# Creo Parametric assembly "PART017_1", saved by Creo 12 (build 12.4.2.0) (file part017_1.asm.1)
Units: Custom; MM, KILOGRAM, SECS

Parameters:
  PTC_WM_ITERATION = "0"
  PTC_WM_VERSION = "-.0"
  PTC_WM_LIFECYCLE_STATE = "In Work"
  PTC_WM_LIFECYCLE = "MO_CADDocument"
  PTC_WM_CREATED_BY = "Maximilian Roepper (Z0017RMS: MO)"
  PTC_WM_CREATED_ON = "18-Sep-26 11:36:42 AM"
  PTC_WM_MODIFIED_BY = "Maximilian Roepper (Z0017RMS: MO)"
  PTC_WM_MODIFIED_ON = "18-Sep-26 11:36:46 AM"
  PDMLINKNUMBER = "PDM000071455131"
  PTC_WM_NUMBER = "PDM000071455131"

Other parameters: WEIGHT, WEIGHT_FACTOR, WEIGHT_ADD, MC_ERRORS, SUPPLIER

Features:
  1. coordinate system
  2. imported feature
  3. component "SHAPESTRING265_1"

Other named items: DRW_VIEW_ORG, ROUGH-GROB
